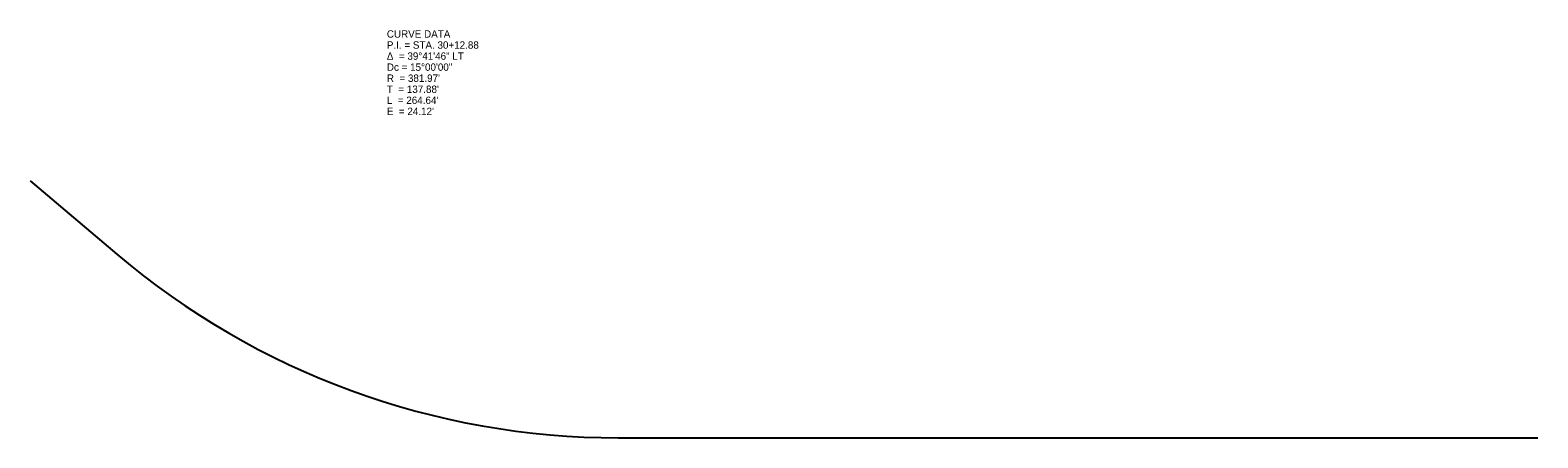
# Model space of a CAD drawing. Extents: x 27634 to 28207, y 6107 to 6262.
import ezdxf

# ---------------------------------------------------------------- set-up
doc = ezdxf.new("R2010")
doc.units = 0
doc.layers.add('BR_X_SV_Deck_Top', color=7, linetype='Continuous')
doc.layers.add('RW_X_CL', color=7, linetype='Continuous')

msp = doc.modelspace()

# ---------------------------------------------------------------- linework, layer by layer
at = {"layer": 'RW_X_CL'}
for p, q in [((27634.21, 6204.29), (27667.13, 6176.45)), ((27857.78, 6106.66), (28207.41, 6106.66))]:
    msp.add_line(p, q, dxfattribs=at)
msp.add_arc((27857.78, 6401.93), 295.28, 229.785, 270, dxfattribs=at)

# ---------------------------------------------------------------- texts
at = {"layer": 'BR_X_SV_Deck_Top'}
for s, p in [('CURVE DATA', (27769.82, 6258.74)), ('P.I. = STA. 30+12.88', (27769.82, 6254.54)), ('Δ  = 39°41\'46" LT', (27769.82, 6250.34)), ('Dc = 15°00\'00"', (27769.82, 6246.14)), ("R  = 381.97'", (27769.82, 6241.94)), ("T  = 137.88'", (27769.82, 6237.74)), ("L  = 264.64'", (27769.82, 6233.54)), ("E  = 24.12'", (27769.82, 6229.34))]:
    msp.add_text(s, height=2.8, dxfattribs=at).set_placement(p)

doc.saveas('drawing.dxf')
